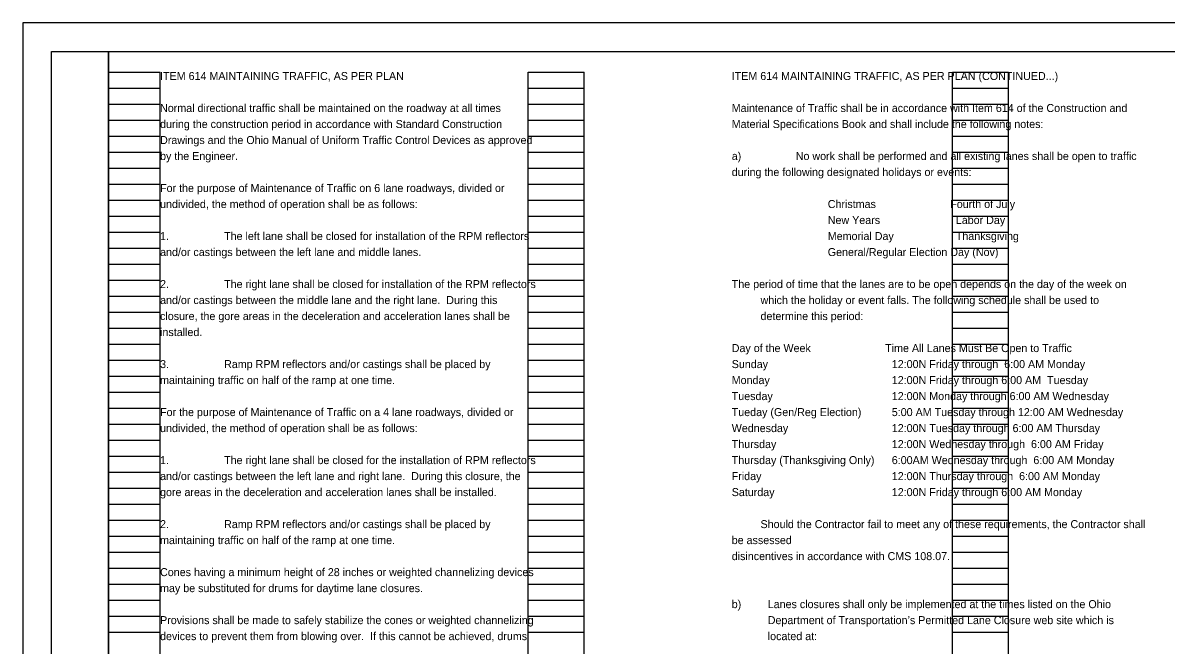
# Model space of a CAD drawing. Extents: x 0 to 34, y 0 to 22.
# Drawn here: x 0 to 20, y 11.11 to 22 of the extents above; entities that cross this region are included whole.
import ezdxf

# ---------------------------------------------------------------- set-up
doc = ezdxf.new("R2010")
doc.units = 0
for name, color, linetype in [('Default', 7, 'Continuous'), ('SH_Border', 7, 'Continuous'), ('SH_Cut_Line', 7, 'Continuous'), ('SH_Data', 7, 'Continuous'), ('SH_Text', 7, 'Continuous')]:
    doc.layers.add(name, color=color, linetype=linetype)

msp = doc.modelspace()

# ---------------------------------------------------------------- linework, layer by layer
at = {"layer": 'SH_Border'}
for points in [[(0.5, 21.5), (1.5, 21.5), (1.5, 0.5), (0.5, 0.5)], [(1.5, 21.5), (33.5, 21.5), (33.5, 0.5), (1.5, 0.5)]]:
    msp.add_lwpolyline(points, close=True, dxfattribs=at)
at = {"layer": 'SH_Cut_Line'}
msp.add_lwpolyline([(0, 0), (34, 0), (34, 22), (0, 22)], close=True, dxfattribs=at)
at = {"layer": 'SH_Data'}
for p, q in [((1.5, 0.98), (1.5, 21.14)), ((1.5, 21.14), (2.4, 21.14)), ((2.4, 0.98), (2.4, 21.14)), ((8.84, 0.98), (8.84, 21.14)), ((8.84, 21.14), (9.82, 21.14)), ((9.82, 0.98), (9.82, 21.14)), ((16.26, 0.98), (16.26, 21.14)), ((16.26, 21.14), (17.24, 21.14)), ((17.24, 0.98), (17.24, 21.14)), ((1.5, 20.86), (2.4, 20.86)), ((8.84, 20.86), (9.82, 20.86)), ((16.26, 20.86), (17.24, 20.86)), ((1.5, 20.58), (2.4, 20.58)), ((8.84, 20.58), (9.82, 20.58)), ((16.26, 20.58), (17.24, 20.58)), ((1.5, 20.3), (2.4, 20.3)), ((8.84, 20.3), (9.82, 20.3)), ((16.26, 20.3), (17.24, 20.3)), ((1.5, 20.02), (2.4, 20.02)), ((8.84, 20.02), (9.82, 20.02)), ((16.26, 20.02), (17.24, 20.02)), ((1.5, 19.74), (2.4, 19.74)), ((8.84, 19.74), (9.82, 19.74)), ((16.26, 19.74), (17.24, 19.74)), ((1.5, 19.46), (2.4, 19.46)), ((8.84, 19.46), (9.82, 19.46)), ((16.26, 19.46), (17.24, 19.46)), ((1.5, 19.18), (2.4, 19.18)), ((8.84, 19.18), (9.82, 19.18)), ((16.26, 19.18), (17.24, 19.18)), ((1.5, 18.9), (2.4, 18.9)), ((8.84, 18.9), (9.82, 18.9)), ((16.26, 18.9), (17.24, 18.9)), ((1.5, 18.62), (2.4, 18.62)), ((8.84, 18.62), (9.82, 18.62)), ((16.26, 18.62), (17.24, 18.62)), ((1.5, 18.34), (2.4, 18.34)), ((8.84, 18.34), (9.82, 18.34)), ((16.26, 18.34), (17.24, 18.34)), ((1.5, 18.06), (2.4, 18.06)), ((8.84, 18.06), (9.82, 18.06)), ((16.26, 18.06), (17.24, 18.06)), ((1.5, 17.78), (2.4, 17.78)), ((8.84, 17.78), (9.82, 17.78)), ((16.26, 17.78), (17.24, 17.78)), ((1.5, 17.5), (2.4, 17.5)), ((8.84, 17.5), (9.82, 17.5)), ((16.26, 17.5), (17.24, 17.5)), ((1.5, 17.22), (2.4, 17.22)), ((8.84, 17.22), (9.82, 17.22)), ((16.26, 17.22), (17.24, 17.22)), ((1.5, 16.94), (2.4, 16.94)), ((8.84, 16.94), (9.82, 16.94)), ((16.26, 16.94), (17.24, 16.94)), ((1.5, 16.66), (2.4, 16.66)), ((8.84, 16.66), (9.82, 16.66)), ((16.26, 16.66), (17.24, 16.66)), ((1.5, 16.38), (2.4, 16.38)), ((8.84, 16.38), (9.82, 16.38)), ((16.26, 16.38), (17.24, 16.38)), ((1.5, 16.1), (2.4, 16.1)), ((8.84, 16.1), (9.82, 16.1)), ((16.26, 16.1), (17.24, 16.1)), ((1.5, 15.82), (2.4, 15.82)), ((8.84, 15.82), (9.82, 15.82)), ((16.26, 15.82), (17.24, 15.82)), ((1.5, 15.54), (2.4, 15.54)), ((8.84, 15.54), (9.82, 15.54)), ((16.26, 15.54), (17.24, 15.54)), ((1.5, 15.26), (2.4, 15.26)), ((8.84, 15.26), (9.82, 15.26)), ((16.26, 15.26), (17.24, 15.26)), ((1.5, 14.98), (2.4, 14.98)), ((8.84, 14.98), (9.82, 14.98)), ((16.26, 14.98), (17.24, 14.98)), ((1.5, 14.7), (2.4, 14.7)), ((8.84, 14.7), (9.82, 14.7)), ((16.26, 14.7), (17.24, 14.7)), ((1.5, 14.42), (2.4, 14.42)), ((8.84, 14.42), (9.82, 14.42)), ((16.26, 14.42), (17.24, 14.42)), ((1.5, 14.14), (2.4, 14.14)), ((8.84, 14.14), (9.82, 14.14)), ((16.26, 14.14), (17.24, 14.14)), ((1.5, 13.86), (2.4, 13.86)), ((8.84, 13.86), (9.82, 13.86)), ((16.26, 13.86), (17.24, 13.86)), ((1.5, 13.58), (2.4, 13.58)), ((8.84, 13.58), (9.82, 13.58)), ((16.26, 13.58), (17.24, 13.58)), ((1.5, 13.3), (2.4, 13.3)), ((8.84, 13.3), (9.82, 13.3)), ((16.26, 13.3), (17.24, 13.3)), ((1.5, 13.02), (2.4, 13.02)), ((8.84, 13.02), (9.82, 13.02)), ((16.26, 13.02), (17.24, 13.02)), ((1.5, 12.74), (2.4, 12.74)), ((8.84, 12.74), (9.82, 12.74)), ((16.26, 12.74), (17.24, 12.74)), ((1.5, 12.46), (2.4, 12.46)), ((8.84, 12.46), (9.82, 12.46)), ((16.26, 12.46), (17.24, 12.46)), ((1.5, 12.18), (2.4, 12.18)), ((8.84, 12.18), (9.82, 12.18)), ((16.26, 12.18), (17.24, 12.18)), ((1.5, 11.9), (2.4, 11.9)), ((8.84, 11.9), (9.82, 11.9)), ((16.26, 11.9), (17.24, 11.9)), ((1.5, 11.62), (2.4, 11.62)), ((8.84, 11.62), (9.82, 11.62)), ((16.26, 11.62), (17.24, 11.62)), ((1.5, 11.34), (2.4, 11.34)), ((8.84, 11.34), (9.82, 11.34)), ((16.26, 11.34), (17.24, 11.34))]:
    msp.add_line(p, q, dxfattribs=at)

# ---------------------------------------------------------------- texts
at = {"layer": 'Default'}
for s, p in [('ITEM 614 MAINTAINING TRAFFIC, AS PER PLAN', (2.4, 21)), ('ITEM 614 MAINTAINING TRAFFIC, AS PER PLAN (CONTINUED...)', (12.4, 21))]:
    msp.add_text(s, height=0.14, dxfattribs=at).set_placement(p)
at = {"layer": 'SH_Text'}
for s, p in [('Normal directional traffic shall be maintained on the roadway at all times ', (2.4, 20.44)), ('Maintenance of Traffic shall be in accordance with Item 614 of the Construction and ', (12.4, 20.44)), ('during the construction period in accordance with Standard Construction ', (2.4, 20.16)), ('Material Specifications Book and shall include the following notes:', (12.4, 20.16)), ('Drawings and the Ohio Manual of Uniform Traffic Control Devices as approved ', (2.4, 19.88)), ('by the Engineer.  ', (2.4, 19.6)), ('a)', (12.4, 19.6)), ('No work shall be performed and all existing lanes shall be open to traffic ', (13.52, 19.6)), ('during the following designated holidays or events:', (12.4, 19.32)), ('For the purpose of Maintenance of Traffic on 6 lane roadways, divided or ', (2.4, 19.04)), ('undivided, the method of operation shall be as follows:', (2.4, 18.76)), ('Christmas                         Fourth of July', (14.08, 18.76)), ('New Years           ', (14.08, 18.48)), ('Labor Day', (16.32, 18.48)), ('1.', (2.4, 18.2)), ('The left lane shall be closed for installation of the RPM reflectors ', (3.52, 18.2)), ('Memorial Day     ', (14.08, 18.2)), ('Thanksgiving', (16.32, 18.2)), ('and/or castings between the left lane and middle lanes.', (2.4, 17.92)), ('General/Regular Election Day (Nov)', (14.08, 17.92)), ('2.', (2.4, 17.36)), ('The right lane shall be closed for installation of the RPM reflectors ', (3.52, 17.36)), ('The period of time that the lanes are to be open depends on the day of the week on ', (12.4, 17.36)), ('and/or castings between the middle lane and the right lane.  During this ', (2.4, 17.08)), ('which the holiday or event falls. The following schedule shall be used to ', (12.904, 17.08)), ('closure, the gore areas in the deceleration and acceleration lanes shall be ', (2.4, 16.8)), ('determine this period:', (12.904, 16.8)), ('installed.', (2.4, 16.52)), ('Day of the Week                         Time All Lanes Must Be Open to Traffic', (12.4, 16.24)), ('3.', (2.4, 15.96)), ('Ramp RPM reflectors and/or castings shall be placed by ', (3.52, 15.96)), ('Sunday    ', (12.4, 15.96)), ('12:00N Friday through  6:00 AM Monday', (15.2, 15.96)), ('maintaining traffic on half of the ramp at one time. ', (2.4, 15.68)), ('Monday ', (12.4, 15.68)), ('12:00N Friday through 6:00 AM  Tuesday', (15.2, 15.68)), ('Tuesday ', (12.4, 15.4)), ('12:00N Monday through 6:00 AM Wednesday', (15.2, 15.4)), ('For the purpose of Maintenance of Traffic on a 4 lane roadways, divided or ', (2.4, 15.12)), ('Tueday (Gen/Reg Election)', (12.4, 15.12)), ('5:00 AM Tuesday through 12:00 AM Wednesday', (15.2, 15.12)), ('undivided, the method of operation shall be as follows:', (2.4, 14.84)), ('Wednesday ', (12.4, 14.84)), ('12:00N Tuesday through 6:00 AM Thursday', (15.2, 14.84)), ('Thursday ', (12.4, 14.56)), ('12:00N Wednesday through  6:00 AM Friday', (15.2, 14.56)), ('1.', (2.4, 14.28)), ('The right lane shall be closed for the installation of RPM reflectors ', (3.52, 14.28)), ('Thursday (Thanksgiving Only) ', (12.4, 14.28)), ('6:00AM Wednesday through  6:00 AM Monday', (15.2, 14.28)), ('and/or castings between the left lane and right lane.  During this closure, the ', (2.4, 14)), ('Friday ', (12.4, 14)), ('12:00N Thursday through  6:00 AM Monday', (15.2, 14)), ('gore areas in the deceleration and acceleration lanes shall be installed.', (2.4, 13.72)), ('Saturday ', (12.4, 13.72)), ('12:00N Friday through 6:00 AM Monday', (15.2, 13.72)), ('2.', (2.4, 13.16)), ('Ramp RPM reflectors and/or castings shall be placed by ', (3.52, 13.16)), ('Should the Contractor fail to meet any of these requirements, the Contractor shall ', (12.904, 13.16)), ('maintaining traffic on half of the ramp at one time. ', (2.4, 12.88)), ('be assessed', (12.4, 12.88)), ('disincentives in accordance with CMS 108.07.', (12.4, 12.6)), ('Cones having a minimum height of 28 inches or weighted channelizing devices ', (2.4, 12.32)), ('may be substituted for drums for daytime lane closures.  ', (2.4, 12.04)), ('b)', (12.4, 11.76)), ('Lanes closures shall only be implemented at the times listed on the Ohio ', (13.03, 11.76)), ('Provisions shall be made to safely stabilize the cones or weighted channelizing ', (2.4, 11.48)), ('Department of Transportation’s Permitted Lane Closure web site which is ', (13.03, 11.48)), ('devices to prevent them from blowing over.  If this cannot be achieved, drums ', (2.4, 11.2)), ('located at:   ', (13.03, 11.2))]:
    msp.add_text(s, height=0.14, dxfattribs=at).set_placement(p)

doc.saveas('drawing.dxf')
